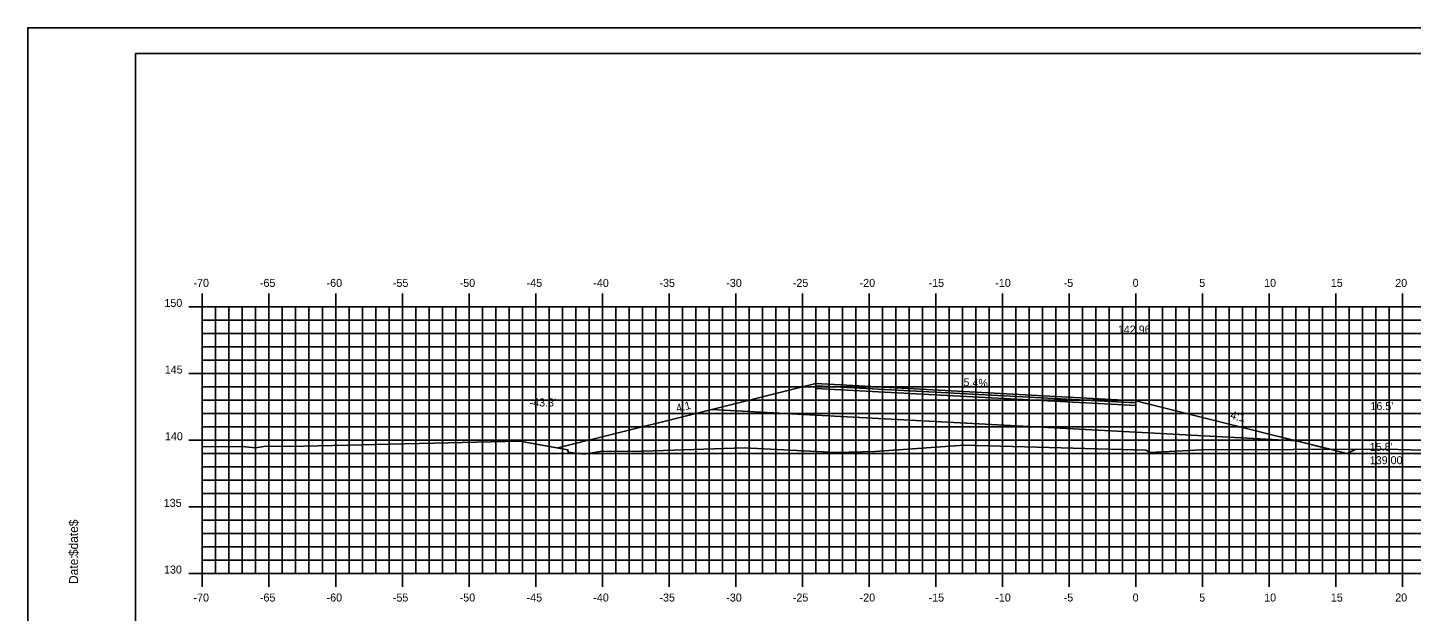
# Model space of a CAD drawing. Extents: x 851417 to 851588, y 365876 to 365986.
# Drawn here: x 851416.8 to 851520.6, y 365942 to 365985.8 of the extents above; entities that cross this region are included whole.
import ezdxf

# ---------------------------------------------------------------- set-up
doc = ezdxf.new("R2010")
doc.units = 0
for name, color, linetype in [('ANNOTATION', 7, 'Continuous'), ('BORDER', 7, 'Continuous'), ('D_Roadway_Centerline', 7, 'Continuous'), ('D_Roadway_Centerline_Text', 7, 'Continuous'), ('D_Roadway_Edge_TW', 7, 'Continuous'), ('D_Roadway_FinishedGrade', 7, 'Continuous'), ('D_Roadway_Pavement', 7, 'Continuous'), ('D_Roadway_SlopeLines', 7, 'Continuous'), ('D_Roadway_SubGrade', 7, 'Continuous'), ('D_Text_Standard', 7, 'Continuous'), ('H_V ANNOTATION', 7, 'Continuous'), ('MAJOR', 7, 'Continuous'), ('MINOR', 7, 'Continuous'), ('PLOT BOUNDARY', 7, 'Continuous'), ('S_Roadway_Centerline', 7, 'Continuous')]:
    doc.layers.add(name, color=color, linetype=linetype)

msp = doc.modelspace()

# ---------------------------------------------------------------- linework, layer by layer
at = {"layer": 'BORDER'}
msp.add_lwpolyline([(851424.9, 365878.83), (851584.9, 365878.83), (851584.9, 365983.83), (851424.9, 365983.83)], close=True, dxfattribs=at)
at = {"layer": 'D_Roadway_Centerline'}
msp.add_lwpolyline([(851456.56, 365954.25), (851465.9, 365956.59), (851475.9, 365959.09), (851499.9, 365957.79), (851509.9, 365955.29), (851514.48, 365954.15)], dxfattribs=at)
at = {"layer": 'D_Roadway_Edge_TW'}
msp.add_lwpolyline([(851475.9, 365959.09), (851499.9, 365957.79), (851499.9, 365957.63), (851475.9, 365958.92)], close=True, dxfattribs=at)
at = {"layer": 'D_Roadway_FinishedGrade'}
for p, q in [((851475.9, 365956.72), (851468.11, 365957.14)), ((851499.9, 365955.43), (851511.97, 365954.78)), ((851515.74, 365953.83), (851516.39, 365954.16))]:
    msp.add_line(p, q, dxfattribs=at)
at = {"layer": 'D_Roadway_Pavement'}
msp.add_lwpolyline([(851475.9, 365958.92), (851499.9, 365957.63), (851499.9, 365957.43), (851475.9, 365958.72)], close=True, dxfattribs=at)
msp.add_lwpolyline([(851499.9, 365957.63), (851499.9, 365957.43)], dxfattribs=at)
msp.add_lwpolyline([(851499.9, 365957.63), (851499.9, 365957.43)], dxfattribs=at)
at = {"layer": 'D_Roadway_SlopeLines'}
for points in [[(851475.9, 365959.09), (851465.9, 365956.59), (851456.56, 365954.25)], [(851499.9, 365957.79), (851509.9, 365955.29), (851515.74, 365953.83)]]:
    msp.add_lwpolyline(points, dxfattribs=at)
at = {"layer": 'D_Roadway_SubGrade'}
for points in [[(851475.9, 365958.72), (851499.9, 365957.43)], [(851499.9, 365955.43), (851475.9, 365956.72)]]:
    msp.add_lwpolyline(points, dxfattribs=at)
at = {"layer": 'MAJOR'}
for p, q in [((851429.9, 365965.84), (851429.9, 365964.83)), ((851434.9, 365965.84), (851434.9, 365964.83)), ((851439.9, 365965.84), (851439.9, 365964.83)), ((851444.9, 365965.84), (851444.9, 365964.83)), ((851449.9, 365965.84), (851449.9, 365964.83)), ((851454.9, 365965.84), (851454.9, 365964.83)), ((851459.9, 365965.84), (851459.9, 365964.83)), ((851464.9, 365965.84), (851464.9, 365964.83)), ((851469.9, 365965.84), (851469.9, 365964.83)), ((851474.9, 365965.84), (851474.9, 365964.83)), ((851479.9, 365965.84), (851479.9, 365964.83)), ((851484.9, 365965.84), (851484.9, 365964.83)), ((851489.9, 365965.84), (851489.9, 365964.83)), ((851494.9, 365965.84), (851494.9, 365964.83)), ((851499.9, 365965.84), (851499.9, 365964.83)), ((851504.9, 365965.84), (851504.9, 365964.83)), ((851509.9, 365965.84), (851509.9, 365964.83)), ((851514.9, 365965.84), (851514.9, 365964.83)), ((851519.9, 365965.84), (851519.9, 365964.83)), ((851428.9, 365964.83), (851429.9, 365964.83)), ((851429.9, 365964.83), (851569.9, 365964.83)), ((851429.9, 365944.83), (851429.9, 365964.83)), ((851429.9, 365944.83), (851429.9, 365964.83)), ((851429.9, 365964.83), (851569.9, 365964.83)), ((851434.9, 365944.83), (851434.9, 365964.83)), ((851439.9, 365944.83), (851439.9, 365964.83)), ((851444.9, 365944.83), (851444.9, 365964.83)), ((851449.9, 365944.83), (851449.9, 365964.83)), ((851454.9, 365944.83), (851454.9, 365964.83)), ((851459.9, 365944.83), (851459.9, 365964.83)), ((851464.9, 365944.83), (851464.9, 365964.83)), ((851469.9, 365944.83), (851469.9, 365964.83)), ((851474.9, 365944.83), (851474.9, 365964.83)), ((851479.9, 365944.83), (851479.9, 365964.83)), ((851484.9, 365944.83), (851484.9, 365964.83)), ((851489.9, 365944.83), (851489.9, 365964.83)), ((851494.9, 365944.83), (851494.9, 365964.83)), ((851499.9, 365944.83), (851499.9, 365964.83)), ((851504.9, 365944.83), (851504.9, 365964.83)), ((851509.9, 365944.83), (851509.9, 365964.83)), ((851514.9, 365944.83), (851514.9, 365964.83)), ((851519.9, 365944.83), (851519.9, 365964.83)), ((851428.9, 365959.83), (851429.9, 365959.83)), ((851429.9, 365959.83), (851569.9, 365959.83)), ((851428.9, 365954.83), (851429.9, 365954.83)), ((851429.9, 365954.83), (851569.9, 365954.83)), ((851428.9, 365949.83), (851429.9, 365949.83)), ((851429.9, 365949.83), (851569.9, 365949.83)), ((851428.9, 365944.83), (851429.9, 365944.83)), ((851429.9, 365944.83), (851569.9, 365944.83)), ((851429.9, 365944.83), (851569.9, 365944.83)), ((851429.9, 365943.83), (851429.9, 365944.83)), ((851434.9, 365943.83), (851434.9, 365944.83)), ((851439.9, 365943.83), (851439.9, 365944.83)), ((851444.9, 365943.83), (851444.9, 365944.83)), ((851449.9, 365943.83), (851449.9, 365944.83)), ((851454.9, 365943.83), (851454.9, 365944.83)), ((851459.9, 365943.83), (851459.9, 365944.83)), ((851464.9, 365943.83), (851464.9, 365944.83)), ((851469.9, 365943.83), (851469.9, 365944.83)), ((851474.9, 365943.83), (851474.9, 365944.83)), ((851479.9, 365943.83), (851479.9, 365944.83)), ((851484.9, 365943.83), (851484.9, 365944.83)), ((851489.9, 365943.83), (851489.9, 365944.83)), ((851494.9, 365943.83), (851494.9, 365944.83)), ((851499.9, 365943.83), (851499.9, 365944.83)), ((851504.9, 365943.83), (851504.9, 365944.83)), ((851509.9, 365943.83), (851509.9, 365944.83)), ((851514.9, 365943.83), (851514.9, 365944.83)), ((851519.9, 365943.83), (851519.9, 365944.83))]:
    msp.add_line(p, q, dxfattribs=at)
at = {"layer": 'MINOR'}
for p, q in [((851430.9, 365944.83), (851430.9, 365964.83)), ((851431.9, 365944.83), (851431.9, 365964.83)), ((851432.9, 365944.83), (851432.9, 365964.83)), ((851433.9, 365944.83), (851433.9, 365964.83)), ((851435.9, 365944.83), (851435.9, 365964.83)), ((851436.9, 365944.83), (851436.9, 365964.83)), ((851437.9, 365944.83), (851437.9, 365964.83)), ((851438.9, 365944.83), (851438.9, 365964.83)), ((851440.9, 365944.83), (851440.9, 365964.83)), ((851441.9, 365944.83), (851441.9, 365964.83)), ((851442.9, 365944.83), (851442.9, 365964.83)), ((851443.9, 365944.83), (851443.9, 365964.83)), ((851445.9, 365944.83), (851445.9, 365964.83)), ((851446.9, 365944.83), (851446.9, 365964.83)), ((851447.9, 365944.83), (851447.9, 365964.83)), ((851448.9, 365944.83), (851448.9, 365964.83)), ((851450.9, 365944.83), (851450.9, 365964.83)), ((851451.9, 365944.83), (851451.9, 365964.83)), ((851452.9, 365944.83), (851452.9, 365964.83)), ((851453.9, 365944.83), (851453.9, 365964.83)), ((851455.9, 365944.83), (851455.9, 365964.83)), ((851456.9, 365944.83), (851456.9, 365964.83)), ((851457.9, 365944.83), (851457.9, 365964.83)), ((851458.9, 365944.83), (851458.9, 365964.83)), ((851460.9, 365944.83), (851460.9, 365964.83)), ((851461.9, 365944.83), (851461.9, 365964.83)), ((851462.9, 365944.83), (851462.9, 365964.83)), ((851463.9, 365944.83), (851463.9, 365964.83)), ((851465.9, 365944.83), (851465.9, 365964.83)), ((851466.9, 365944.83), (851466.9, 365964.83)), ((851467.9, 365944.83), (851467.9, 365964.83)), ((851468.9, 365944.83), (851468.9, 365964.83)), ((851470.9, 365944.83), (851470.9, 365964.83)), ((851471.9, 365944.83), (851471.9, 365964.83)), ((851472.9, 365944.83), (851472.9, 365964.83)), ((851473.9, 365944.83), (851473.9, 365964.83)), ((851475.9, 365944.83), (851475.9, 365964.83)), ((851476.9, 365944.83), (851476.9, 365964.83)), ((851477.9, 365944.83), (851477.9, 365964.83)), ((851478.9, 365944.83), (851478.9, 365964.83)), ((851480.9, 365944.83), (851480.9, 365964.83)), ((851481.9, 365944.83), (851481.9, 365964.83)), ((851482.9, 365944.83), (851482.9, 365964.83)), ((851483.9, 365944.83), (851483.9, 365964.83)), ((851485.9, 365944.83), (851485.9, 365964.83)), ((851486.9, 365944.83), (851486.9, 365964.83)), ((851487.9, 365944.83), (851487.9, 365964.83)), ((851488.9, 365944.83), (851488.9, 365964.83)), ((851490.9, 365944.83), (851490.9, 365964.83)), ((851491.9, 365944.83), (851491.9, 365964.83)), ((851492.9, 365944.83), (851492.9, 365964.83)), ((851493.9, 365944.83), (851493.9, 365964.83)), ((851495.9, 365944.83), (851495.9, 365964.83)), ((851496.9, 365944.83), (851496.9, 365964.83)), ((851497.9, 365944.83), (851497.9, 365964.83)), ((851498.9, 365944.83), (851498.9, 365964.83)), ((851500.9, 365944.83), (851500.9, 365964.83)), ((851501.9, 365944.83), (851501.9, 365964.83)), ((851502.9, 365944.83), (851502.9, 365964.83)), ((851503.9, 365944.83), (851503.9, 365964.83)), ((851505.9, 365944.83), (851505.9, 365964.83)), ((851506.9, 365944.83), (851506.9, 365964.83)), ((851507.9, 365944.83), (851507.9, 365964.83)), ((851508.9, 365944.83), (851508.9, 365964.83)), ((851510.9, 365944.83), (851510.9, 365964.83)), ((851511.9, 365944.83), (851511.9, 365964.83)), ((851512.9, 365944.83), (851512.9, 365964.83)), ((851513.9, 365944.83), (851513.9, 365964.83)), ((851515.9, 365944.83), (851515.9, 365964.83)), ((851516.9, 365944.83), (851516.9, 365964.83)), ((851517.9, 365944.83), (851517.9, 365964.83)), ((851518.9, 365944.83), (851518.9, 365964.83)), ((851429.9, 365963.83), (851569.9, 365963.83)), ((851429.9, 365963.83), (851430.9, 365963.83)), ((851429.9, 365962.83), (851569.9, 365962.83)), ((851429.9, 365962.83), (851430.9, 365962.83)), ((851429.9, 365961.83), (851569.9, 365961.83)), ((851429.9, 365961.83), (851430.9, 365961.83)), ((851429.9, 365960.83), (851569.9, 365960.83)), ((851429.9, 365960.83), (851430.9, 365960.83)), ((851429.9, 365958.83), (851569.9, 365958.83)), ((851429.9, 365958.83), (851430.9, 365958.83)), ((851429.9, 365957.83), (851569.9, 365957.83)), ((851429.9, 365957.83), (851430.9, 365957.83)), ((851429.9, 365956.83), (851569.9, 365956.83)), ((851429.9, 365956.83), (851430.9, 365956.83)), ((851429.9, 365955.83), (851569.9, 365955.83)), ((851429.9, 365955.83), (851430.9, 365955.83)), ((851429.9, 365953.83), (851569.9, 365953.83)), ((851429.9, 365953.83), (851430.9, 365953.83)), ((851429.9, 365952.83), (851569.9, 365952.83)), ((851429.9, 365952.83), (851430.9, 365952.83)), ((851429.9, 365951.83), (851569.9, 365951.83)), ((851429.9, 365951.83), (851430.9, 365951.83)), ((851429.9, 365950.83), (851569.9, 365950.83)), ((851429.9, 365950.83), (851430.9, 365950.83)), ((851429.9, 365948.83), (851569.9, 365948.83)), ((851429.9, 365948.83), (851430.9, 365948.83)), ((851429.9, 365947.83), (851569.9, 365947.83)), ((851429.9, 365947.83), (851430.9, 365947.83)), ((851429.9, 365946.83), (851569.9, 365946.83)), ((851429.9, 365946.83), (851430.9, 365946.83)), ((851429.9, 365945.83), (851569.9, 365945.83)), ((851429.9, 365945.83), (851430.9, 365945.83))]:
    msp.add_line(p, q, dxfattribs=at)
at = {"layer": 'PLOT BOUNDARY'}
msp.add_lwpolyline([(851416.81, 365875.77), (851586.81, 365875.77), (851586.81, 365985.77), (851416.81, 365985.77)], close=True, dxfattribs=at)
at = {"layer": 'S_Roadway_Centerline'}
msp.add_lwpolyline([(851429.9, 365954.33), (851432.89, 365954.36), (851433.9, 365954.27), (851434.52, 365954.35), (851435.39, 365954.38), (851436.43, 365954.35), (851453.7, 365954.75), (851457.31, 365954.12), (851457.33, 365953.93), (851458.54, 365953.78), (851459.74, 365953.98), (851462.98, 365954), (851470.52, 365954.25), (851477.46, 365953.92), (851480.33, 365953.98), (851487.02, 365954.45), (851487.02, 365954.45), (851487.02, 365954.45), (851500.65, 365954.08), (851500.97, 365953.9), (851504.8, 365954.12), (851518.6, 365954.16), (851523.38, 365954.03)], dxfattribs=at)

# ---------------------------------------------------------------- texts
at = {"layer": 'ANNOTATION'}
for s, rotation, p in [('5.4%', 356.909, (851486.96, 365958.89)), ('4:1', 14.0362, (851465.5, 365956.92)), ('4:1', 345.9638, (851506.94, 365956.46))]:
    msp.add_text(s, height=0.6, rotation=rotation, dxfattribs=at).set_placement(p)
at = {"layer": 'BORDER'}
for s, p in [('$date$', (851420.58, 365946.14)), ('Date:', (851420.58, 365944.05))]:
    msp.add_text(s, height=0.67, rotation=90, dxfattribs=at).set_placement(p)
at = {"layer": 'D_Roadway_Centerline_Text'}
msp.add_text('142.96', height=0.6, dxfattribs=at).set_placement((851498.55, 365962.83))
at = {"layer": 'D_Text_Standard'}
for s, p in [("-43.3'", (851454.44, 365957.36)), ("16.5'", (851517.49, 365957.09)), ("15.8' ", (851517.44, 365954.03)), ('139.00', (851517.44, 365953.03))]:
    msp.add_text(s, height=0.6, dxfattribs=at).set_placement(p)
at = {"layer": 'H_V ANNOTATION'}
for s, p in [('-70', (851429.24, 365966.33)), ('-65', (851434.22, 365966.33)), ('-60', (851439.22, 365966.33)), ('-55', (851444.19, 365966.33)), ('-50', (851449.2, 365966.33)), ('-45', (851454.22, 365966.33)), ('-40', (851459.22, 365966.33)), ('-35', (851464.18, 365966.33)), ('-30', (851469.19, 365966.33)), ('-25', (851474.18, 365966.33)), ('-20', (851479.19, 365966.33)), ('-15', (851484.36, 365966.33)), ('-10', (851489.36, 365966.33)), ('-5', (851494.49, 365966.33)), ('0', (851499.66, 365966.33)), ('5', (851504.65, 365966.33)), ('10', (851509.52, 365966.33)), ('15', (851514.52, 365966.33)), ('20', (851519.35, 365966.33)), ('150', (851427.06, 365964.83)), ('145', (851427.09, 365959.83)), ('140', (851427.1, 365954.83)), ('135', (851427.01, 365949.83)), ('130', (851427.03, 365944.83)), ('-70', (851429.24, 365942.73)), ('-65', (851434.22, 365942.73)), ('-60', (851439.22, 365942.73)), ('-55', (851444.19, 365942.73)), ('-50', (851449.2, 365942.73)), ('-45', (851454.22, 365942.73)), ('-40', (851459.22, 365942.73)), ('-35', (851464.18, 365942.73)), ('-30', (851469.19, 365942.73)), ('-25', (851474.18, 365942.73)), ('-20', (851479.19, 365942.73)), ('-15', (851484.36, 365942.73)), ('-10', (851489.36, 365942.73)), ('-5', (851494.49, 365942.73)), ('0', (851499.66, 365942.73)), ('5', (851504.65, 365942.73)), ('10', (851509.52, 365942.73)), ('15', (851514.52, 365942.73)), ('20', (851519.35, 365942.73))]:
    msp.add_text(s, height=0.6, dxfattribs=at).set_placement(p)
at = {"layer": 'MAJOR'}
msp.add_text('-', height=0.006, dxfattribs=at).set_placement((851429.89, 365944.83))

doc.saveas('drawing.dxf')
